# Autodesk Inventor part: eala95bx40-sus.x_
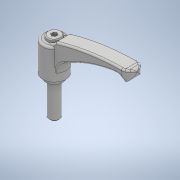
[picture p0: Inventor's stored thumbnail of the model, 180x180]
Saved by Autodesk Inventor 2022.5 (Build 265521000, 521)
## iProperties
Created: 2018-05
Part Number: eala95bx40-sus.x_
Material: 一般
Document SubType Name: Modeling
Designer: imaocorp
Density: 1 g/cm^3
Appearance: 既定
Sending System: SOLIDWORKS 2016-2016286
MC: AMD64
MC_MODEL: AMD64 Family 21 Model 2 Stepping 0, AuthenticAMD
OS: Windows_NT
FRU: Parasolid Version 28.0, build 224,  7-29-2016
FORMAT: text
GUISE: transmit
KEY: eala95bx40-sus
FILE: eala95bx40-sus.x_t
DATE: Fri May 18 11:33:58 2018
Author: imaocorp
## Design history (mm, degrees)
feature "Base1"
node "ソリッド1"
